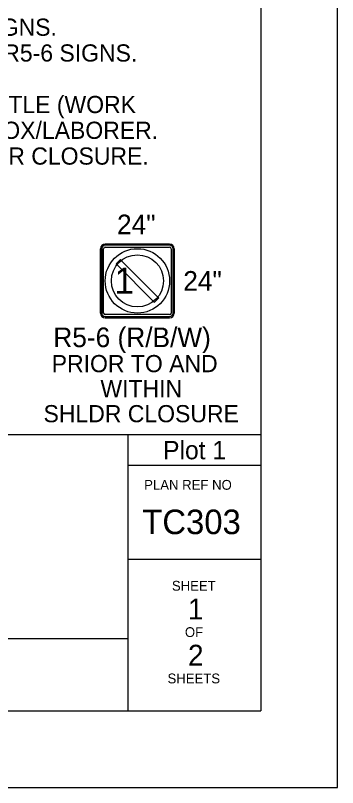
# Model space of a CAD drawing. Extents: x 99999.1 to 100055.7, y 99995 to 100013.2.
# Drawn here: x 100014.75 to 100016.062, y 99999.687 to 100002.833 of the extents above; entities that cross this region are included whole.
import ezdxf

# ---------------------------------------------------------------- set-up
doc = ezdxf.new("R2010")
doc.units = 0
for name, color, linetype in [('SH_GI_GeneralNotesBodyText', 7, 'Continuous'), ('SH_GI_PlotLimits', 7, 'Continuous'), ('SH_GI_SheetBorder', 7, 'Continuous'), ('SH_GI_SheetLocationText', 7, 'Continuous'), ('SH_GI_SheetTextInCells', 7, 'Continuous'), ('SH_GI_TitleBlockText', 7, 'Continuous'), ('TR_SN_ConstructionSigns', 7, 'Continuous')]:
    doc.layers.add(name, color=color, linetype=linetype)

msp = doc.modelspace()

# ---------------------------------------------------------------- linework, layer by layer
at = {"layer": 'SH_GI_PlotLimits'}
msp.add_lwpolyline([(99999.0625, 99999.6875), (100016.0625, 99999.6875), (100016.0625, 100010.6875), (99999.0625, 100010.6875)], close=True, dxfattribs=at)
at = {"layer": 'SH_GI_SheetBorder'}
for p, q in [((100015.75, 100010.375), (100015.75, 100000)), ((100000, 100001.1259), (100015.75, 100001.1259)), ((100015.2079, 100001.1259), (100015.2079, 100000)), ((100015.2079, 100001.0008), (100015.75, 100001.0008)), ((100015.2079, 100000.6176), (100015.75, 100000.6176)), ((100012.2055, 100000.2955), (100015.2079, 100000.2955)), ((100000, 100000), (100015.75, 100000))]:
    msp.add_line(p, q, dxfattribs=at)
at = {"layer": 'TR_SN_ConstructionSigns'}
for p, q in [((100015.3783, 100001.9019), (100015.1158, 100001.9019)), ((100015.1158, 100001.9019), (100015.3783, 100001.9019)), ((100015.3783, 100001.9019), (100015.1158, 100001.9019)), ((100015.3783, 100001.8972), (100015.1158, 100001.8972)), ((100015.1158, 100001.8894), (100015.3783, 100001.8894)), ((100015.0971, 100001.8831), (100015.0971, 100001.6206)), ((100015.0971, 100001.6206), (100015.0971, 100001.8831)), ((100015.0971, 100001.8831), (100015.0971, 100001.6206)), ((100015.1018, 100001.8831), (100015.1018, 100001.6206)), ((100015.1096, 100001.6206), (100015.1096, 100001.8831)), ((100015.3846, 100001.8831), (100015.3846, 100001.6206)), ((100015.3924, 100001.6206), (100015.3924, 100001.8831)), ((100015.3971, 100001.6206), (100015.3971, 100001.8831)), ((100015.3971, 100001.8831), (100015.3971, 100001.6206)), ((100015.3971, 100001.6206), (100015.3971, 100001.8831)), ((100015.3783, 100001.6144), (100015.1158, 100001.6144)), ((100015.1158, 100001.6066), (100015.3783, 100001.6066)), ((100015.1158, 100001.6019), (100015.3783, 100001.6019)), ((100015.3783, 100001.6019), (100015.1158, 100001.6019)), ((100015.1158, 100001.6019), (100015.3783, 100001.6019))]:
    msp.add_line(p, q, dxfattribs=at)
msp.add_lwpolyline([(100015.3305, 100001.6861), (100015.1813, 100001.8353), (100015.1778, 100001.8389), (100015.1601, 100001.8212), (100015.3128, 100001.6685), (100015.3164, 100001.6649), (100015.3341, 100001.6826), (100015.3305, 100001.6861)], dxfattribs=at)
for radius in [0.1313, 0.1062]:
    msp.add_circle((100015.2471, 100001.7519), radius, dxfattribs=at)
for centre, radius, start, end in [((100015.1158, 100001.8831), 0.0187, 90, 180), ((100015.1158, 100001.8831), 0.0187, 90, 180), ((100015.1158, 100001.8831), 0.0187, 90, 180), ((100015.1158, 100001.8831), 0.0141, 90, 180), ((100015.1158, 100001.8831), 0.00625, 90, 180), ((100015.3783, 100001.8831), 0.0187, 0, 90), ((100015.3783, 100001.8831), 0.0187, 0, 90), ((100015.3783, 100001.8831), 0.0187, 0, 90), ((100015.3783, 100001.8831), 0.0141, 0, 90), ((100015.3783, 100001.8831), 0.00625, 0, 90), ((100015.1158, 100001.6206), 0.0187, 180, 270), ((100015.1158, 100001.6206), 0.0187, 180, 270), ((100015.1158, 100001.6206), 0.0187, 180, 270), ((100015.1158, 100001.6206), 0.0141, 180, 270), ((100015.1158, 100001.6206), 0.00625, 180, 270), ((100015.3783, 100001.6206), 0.0141, 270, 0), ((100015.3783, 100001.6206), 0.00625, 270, 0), ((100015.3783, 100001.6206), 0.0187, 270, 0), ((100015.3783, 100001.6206), 0.0187, 270, 0), ((100015.3783, 100001.6206), 0.0187, 270, 0)]:
    msp.add_arc(centre, radius, start, end, dxfattribs=at)

# ---------------------------------------------------------------- texts
at = {"layer": 'SH_GI_GeneralNotesBodyText'}
for s, p in [('(A) SHARED BICYCLE-VEHICLE LANE. ADD W11-15 MOD & R4-11 SIGNS.', (100011.689, 100002.7506)), ('(B) BICYCLES PROHIBITED VIA R5-601 (IF EXIT-RAMP PRESENT) & R5-6 SIGNS. ', (100011.689, 100002.6456)), ('(C) BICYCLES PROHIBITED VIA R5-6 SIGN(S). PROVIDE FREE SHUTTLE (WORK ', (100011.689, 100002.4356)), ('TRUCK, VAN, OR BUS OK) + CONTACT INFORMATION/PHONE BOX/LABORER. ', (100011.839, 100002.3306)), ('(D) STOP WORK OPS. & ESCORT BICYCLISTS THROUGH SHOULDER CLOSURE.', (100011.689, 100002.2256))]:
    msp.add_text(s, height=0.07, rotation=360, dxfattribs=at).set_placement(p)
at = {"layer": 'SH_GI_SheetBorder'}
msp.add_text('PLAN REF NO', height=0.040032, dxfattribs=at).set_placement((100015.2747, 100000.9008))
at = {"layer": 'SH_GI_SheetLocationText'}
msp.add_text('Plot 1', height=0.075, dxfattribs=at).set_placement((100015.3518, 100001.025))
at = {"layer": 'SH_GI_SheetTextInCells'}
for s, p in [('SHEET', (100015.3877, 100000.4896)), ('OF', (100015.4406, 100000.3008)), ('SHEETS', (100015.3698, 100000.112))]:
    msp.add_text(s, height=0.04003, dxfattribs=at).set_placement(p)
at = {"layer": 'SH_GI_TitleBlockText'}
for s, height, p in [('TC303', 0.1, (100015.267, 100000.72)), ('1', 0.085, (100015.4526, 100000.3723)), ('2', 0.085, (100015.4534, 100000.1843))]:
    msp.add_text(s, height=height, dxfattribs=at).set_placement(p)
at = {"layer": 'TR_SN_ConstructionSigns'}
for s, height, p in [('24"', 0.08, (100015.164, 100001.9419)), ('24"', 0.08, (100015.434, 100001.7119)), ('R5-6 (R/B/W)', 0.08, (100014.9045, 100001.4819)), ('PRIOR TO AND', 0.07, (100014.898, 100001.3799)), ('WITHIN', 0.07, (100015.0965, 100001.2779)), ('SHLDR CLOSURE', 0.07, (100014.8647, 100001.1759))]:
    msp.add_text(s, height=height, rotation=360, dxfattribs=at).set_placement(p)
msp.add_text('1', height=0.1065, dxfattribs=at).set_placement((100015.1538, 100001.6994))

doc.saveas('drawing.dxf')
